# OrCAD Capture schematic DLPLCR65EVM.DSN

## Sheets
1 PAGE-05 DMD Power: size D
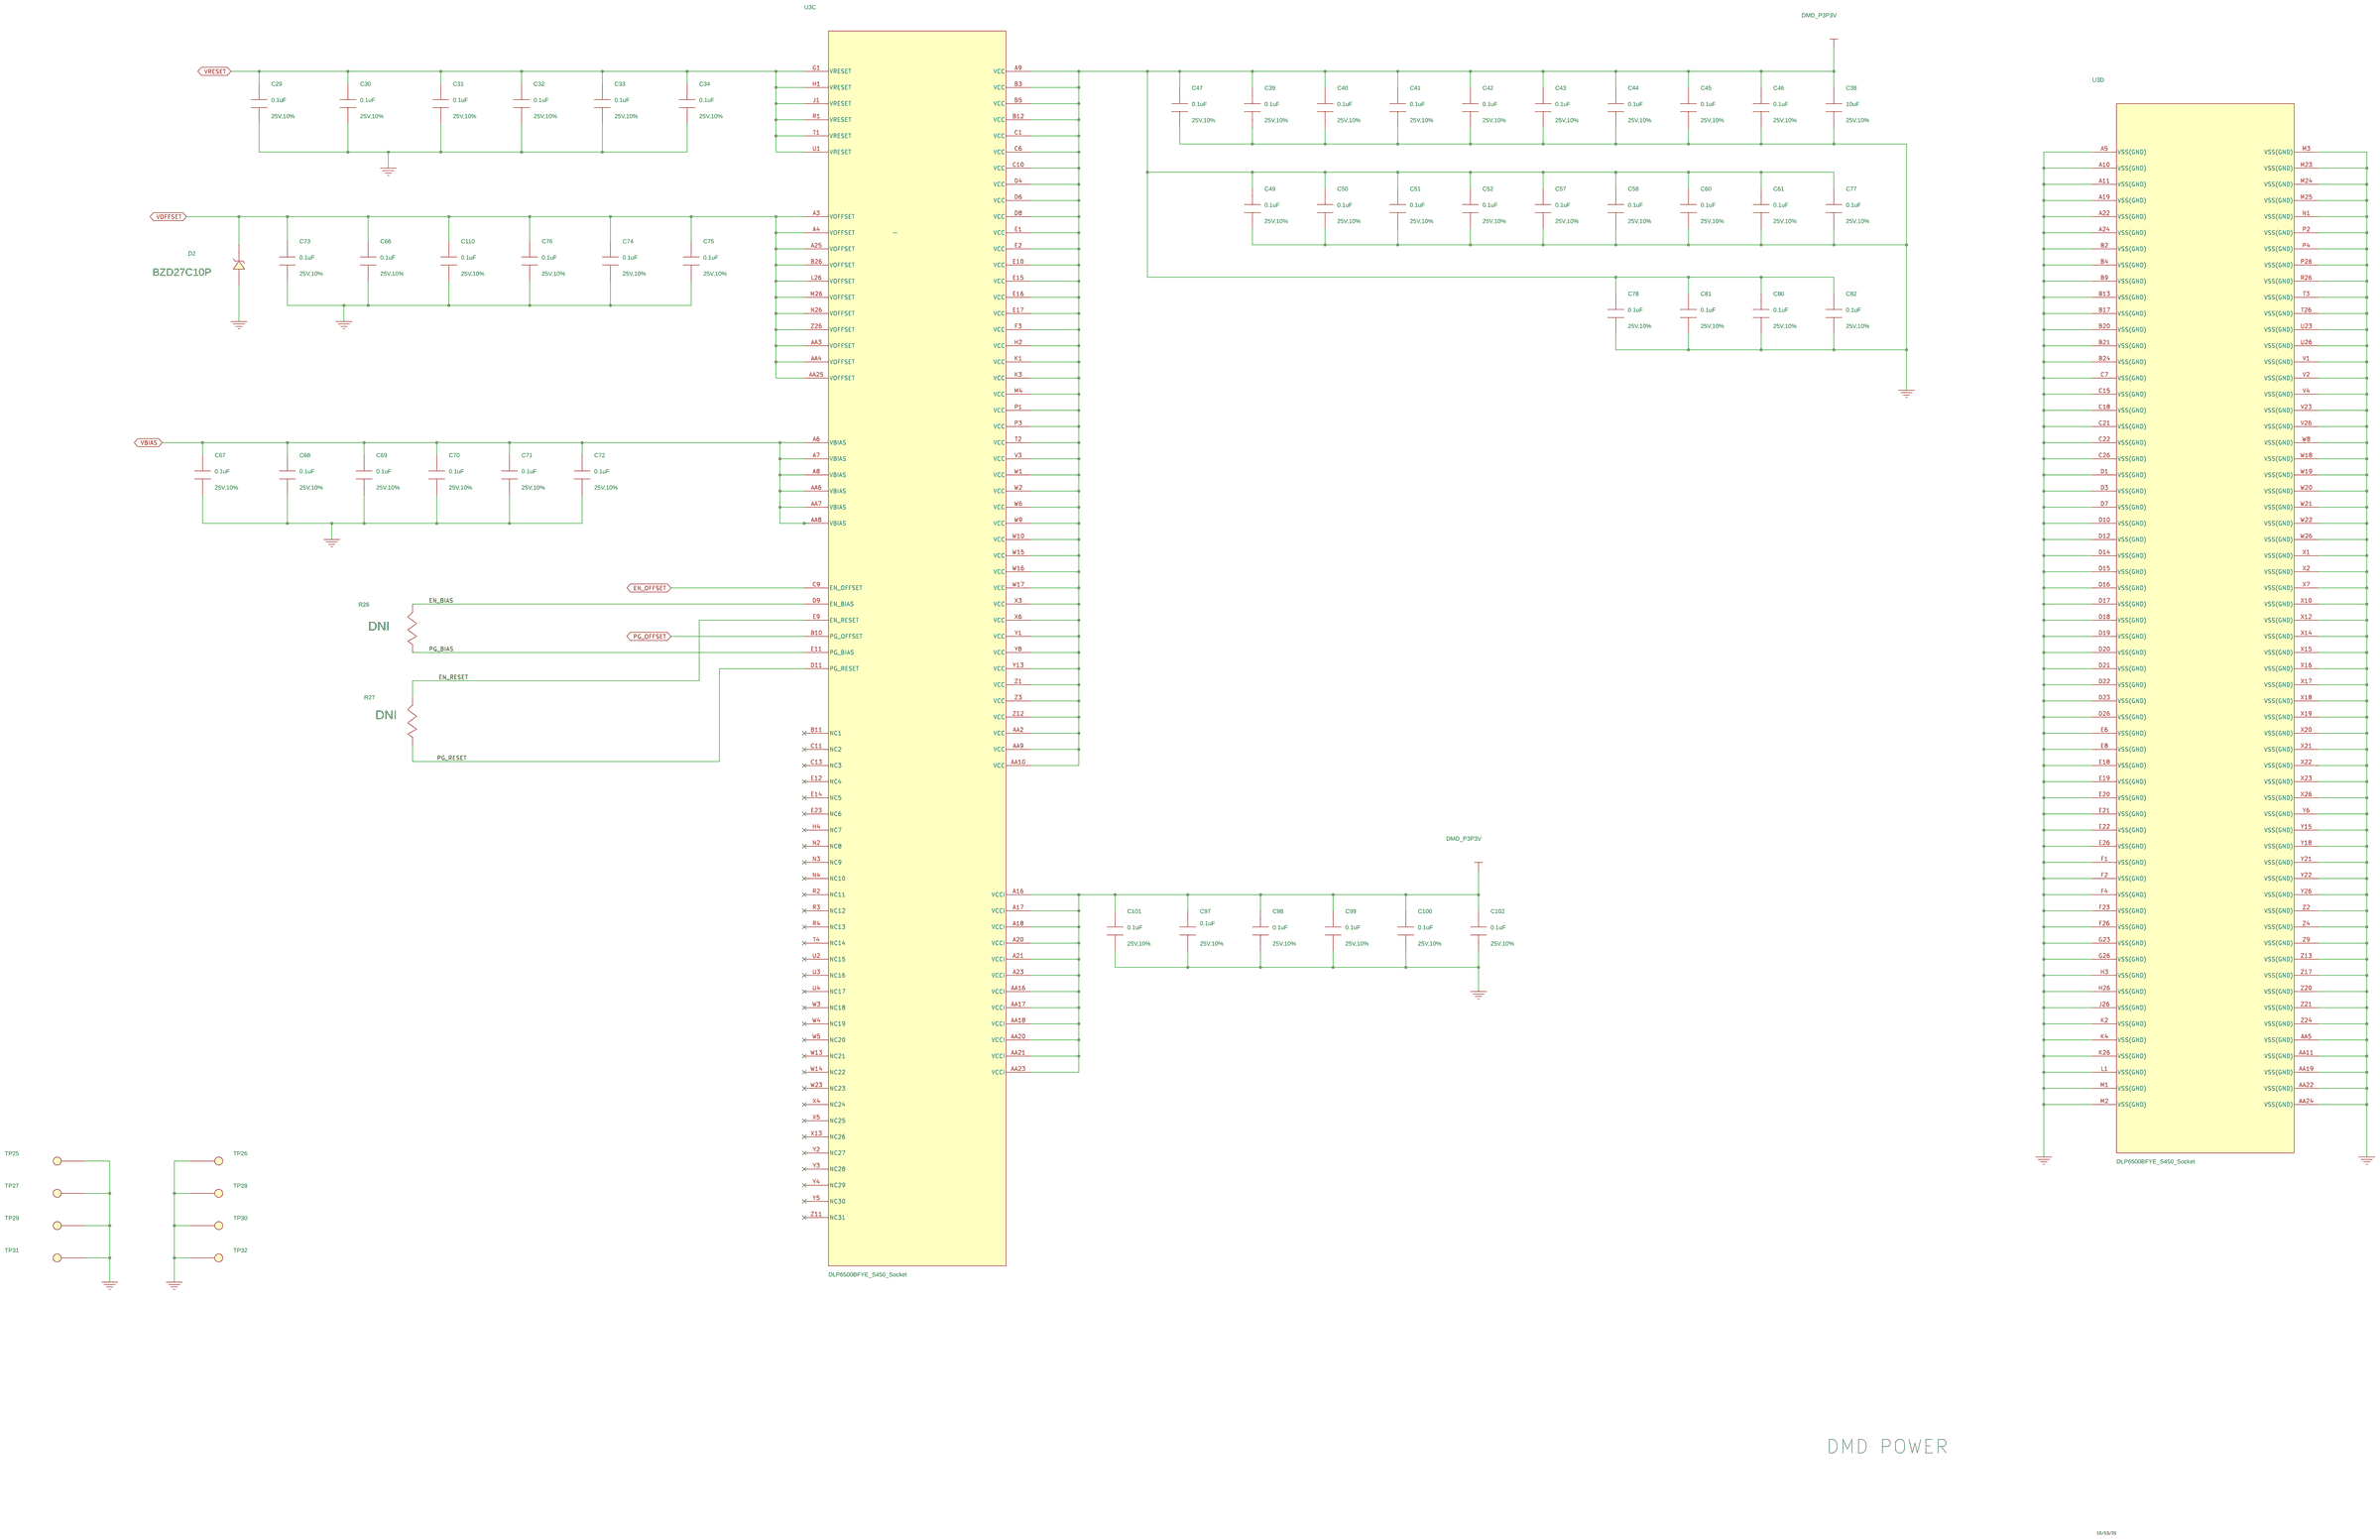
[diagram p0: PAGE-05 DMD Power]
2 PAGE-04 DMD Data Input: size D
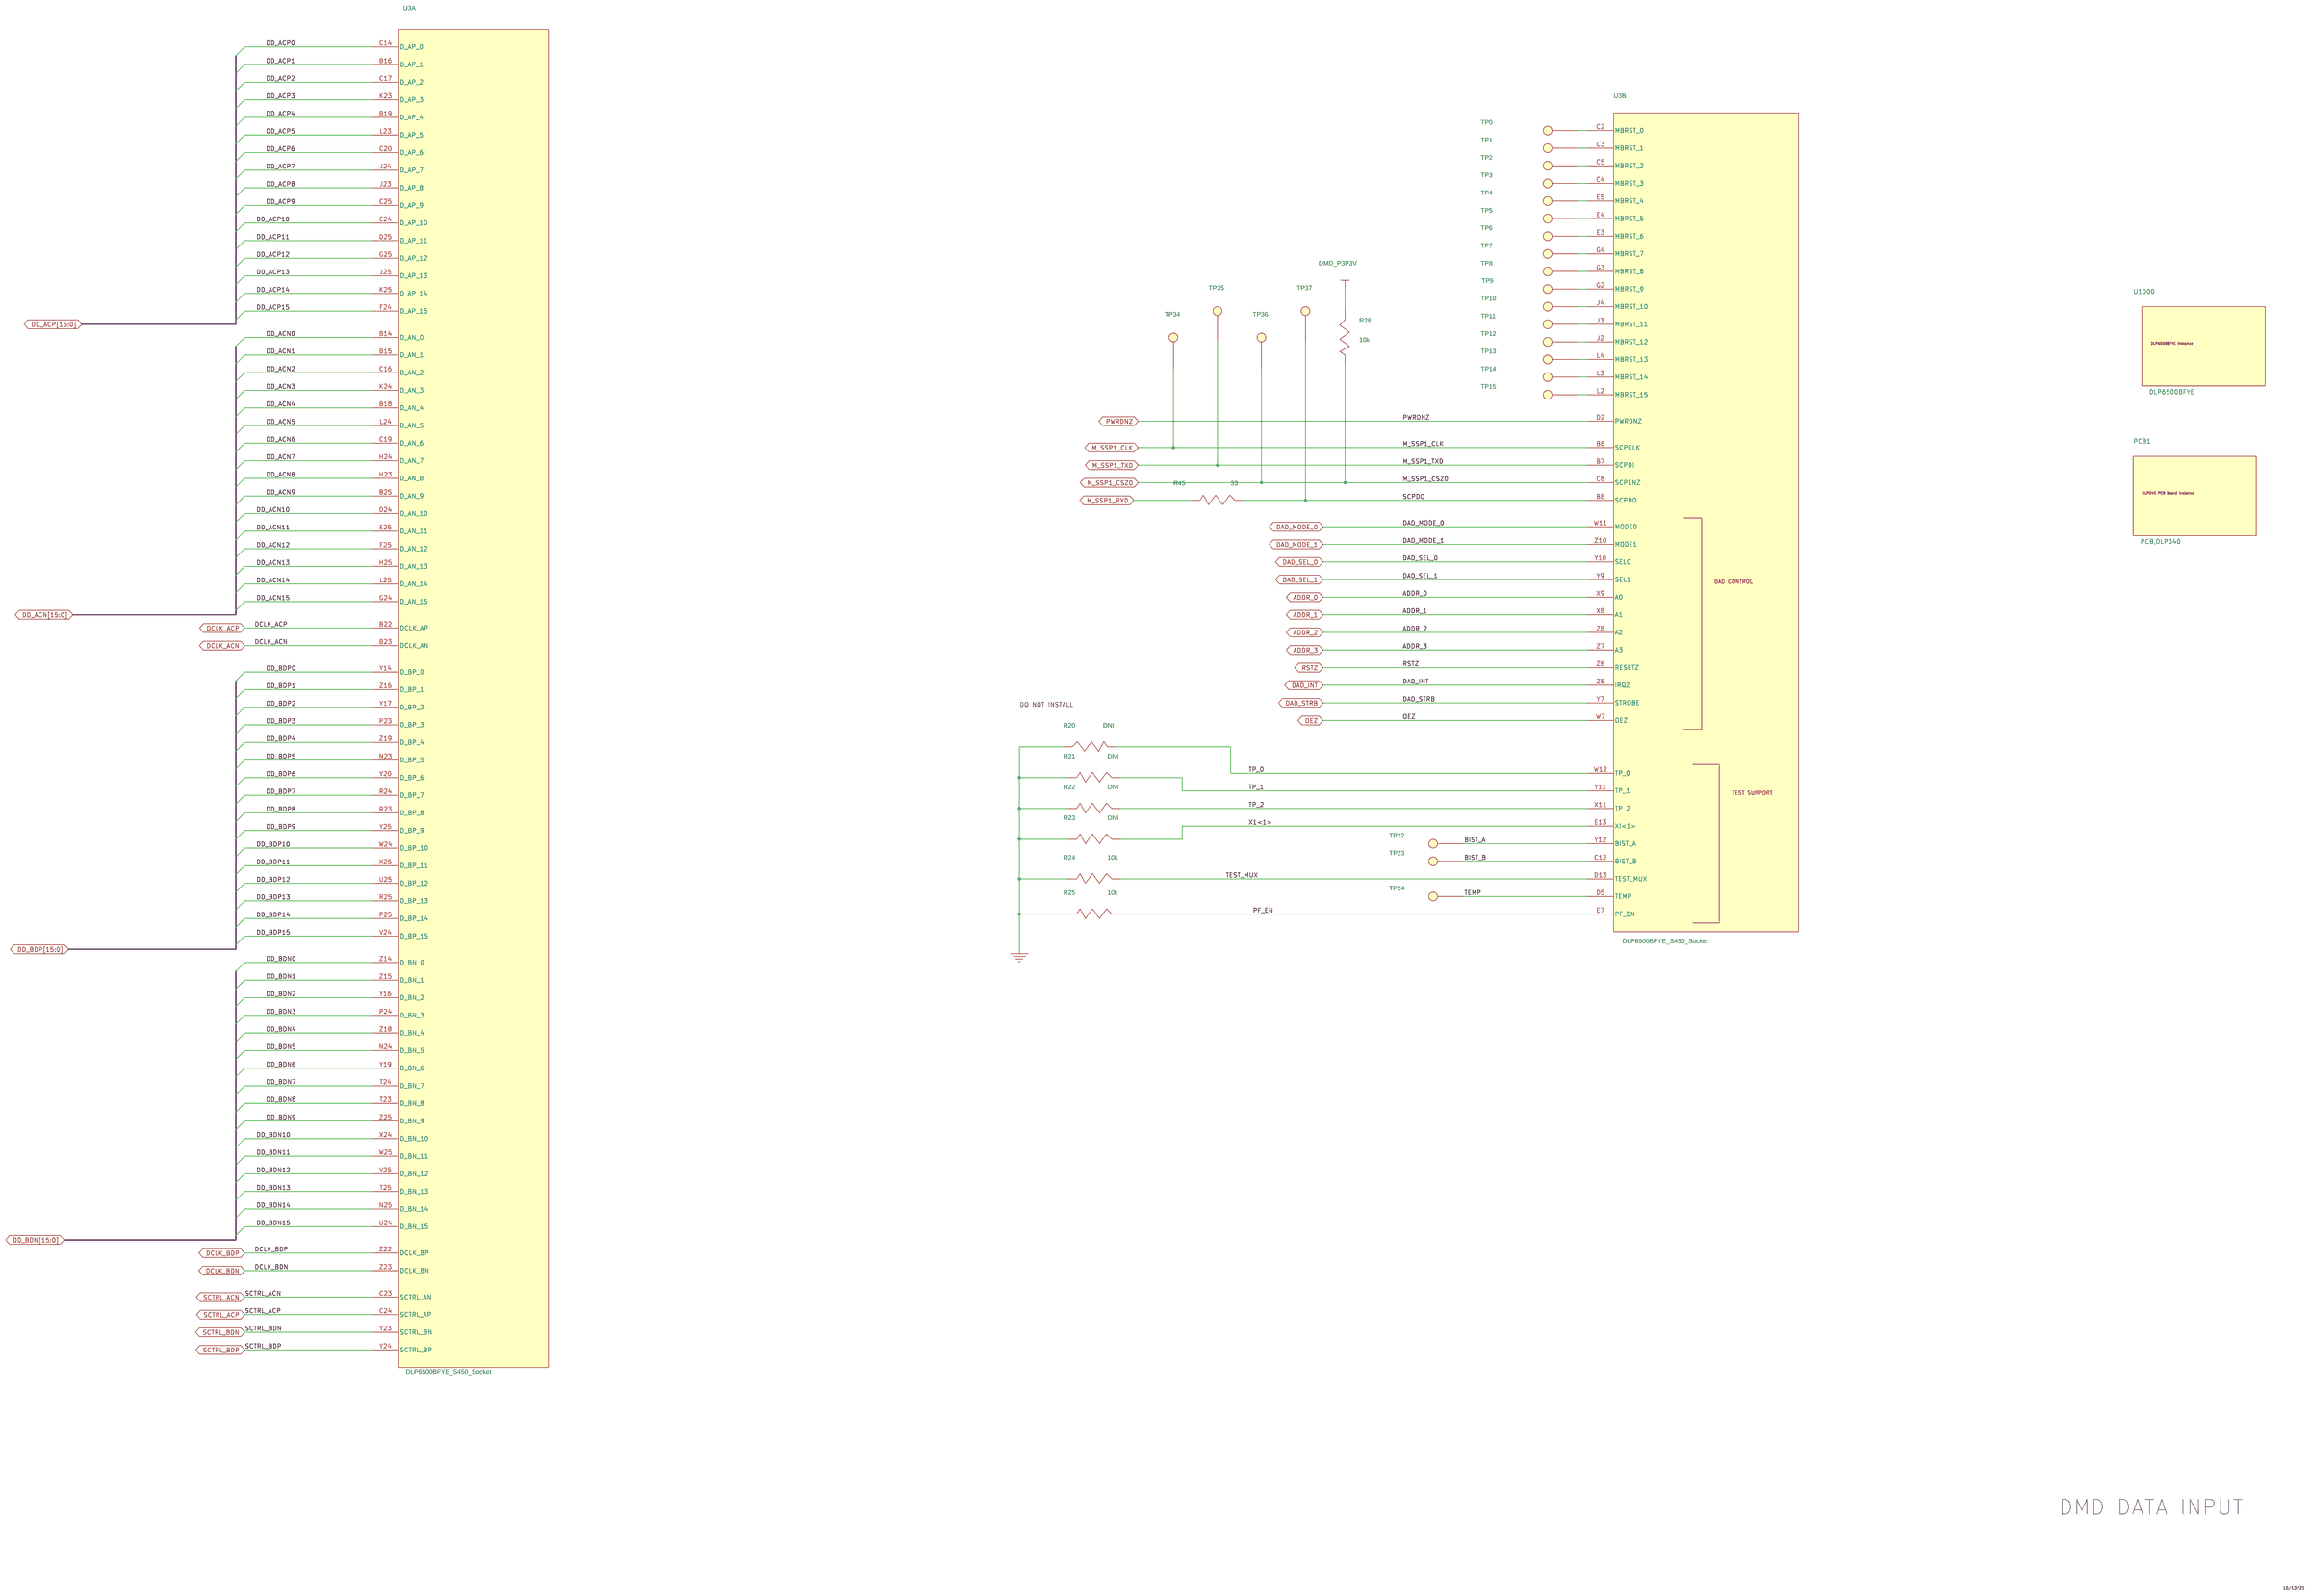
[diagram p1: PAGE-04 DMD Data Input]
3 PAGE-01 Title Page
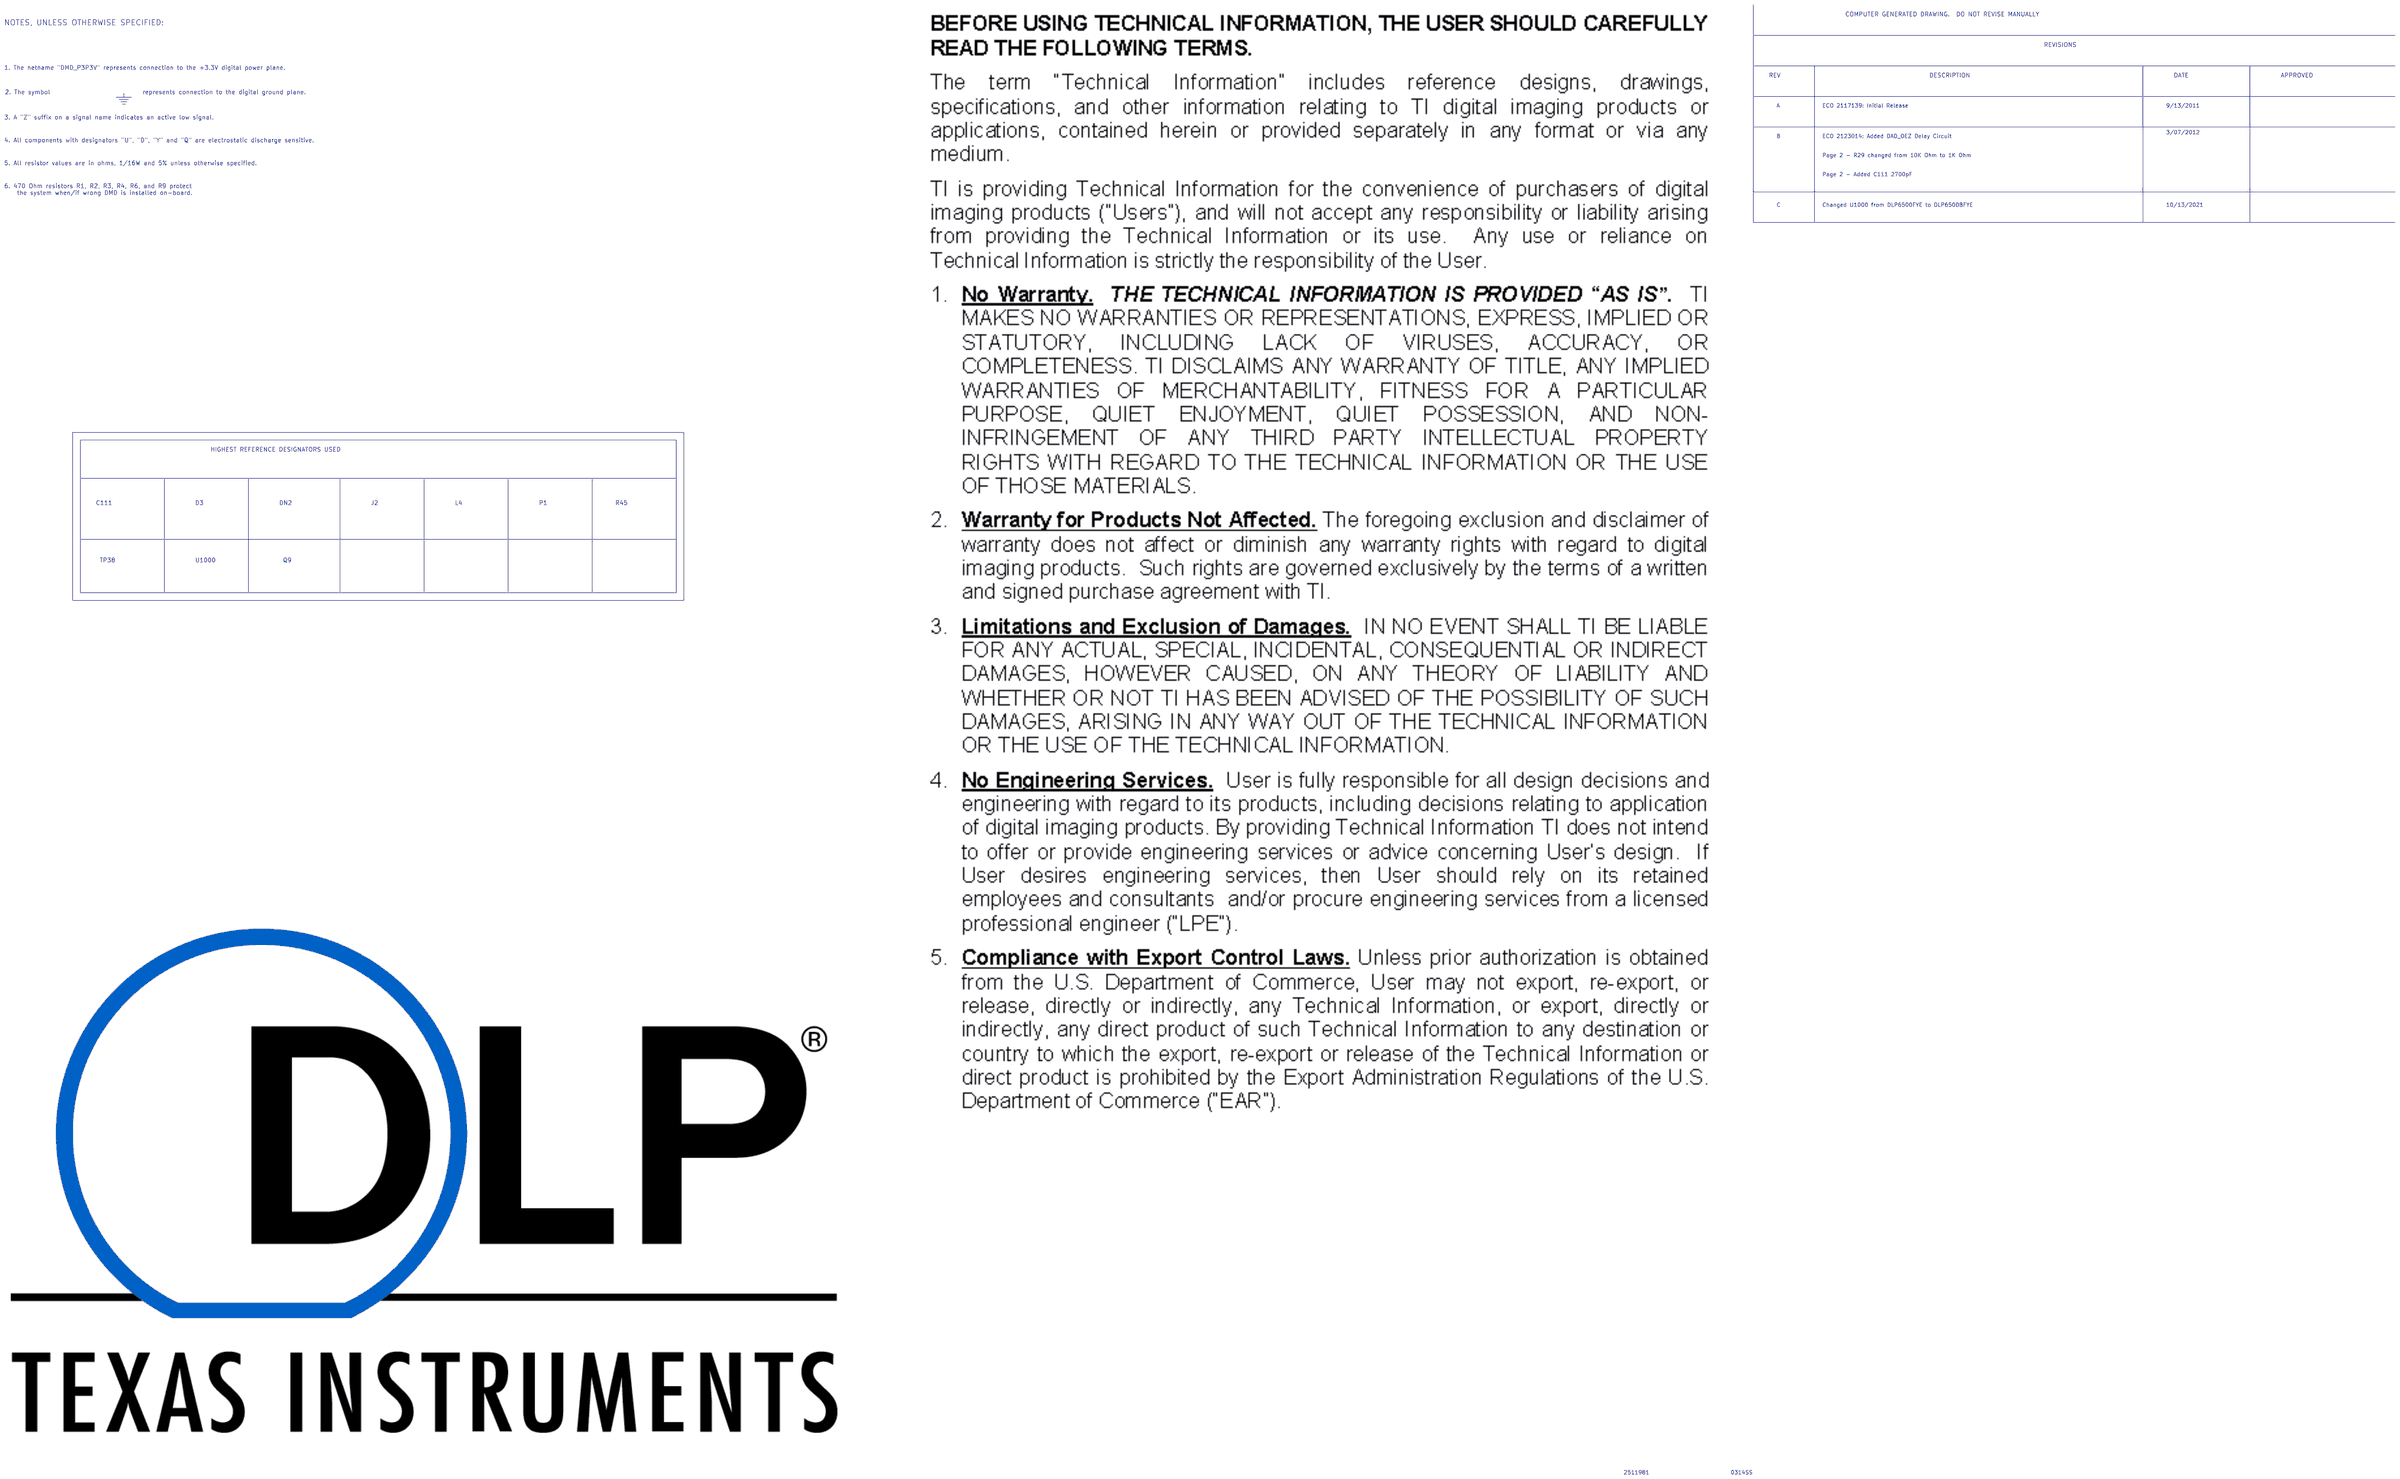
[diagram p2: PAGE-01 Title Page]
4 PAGE-03 DMD Power Supply: size D
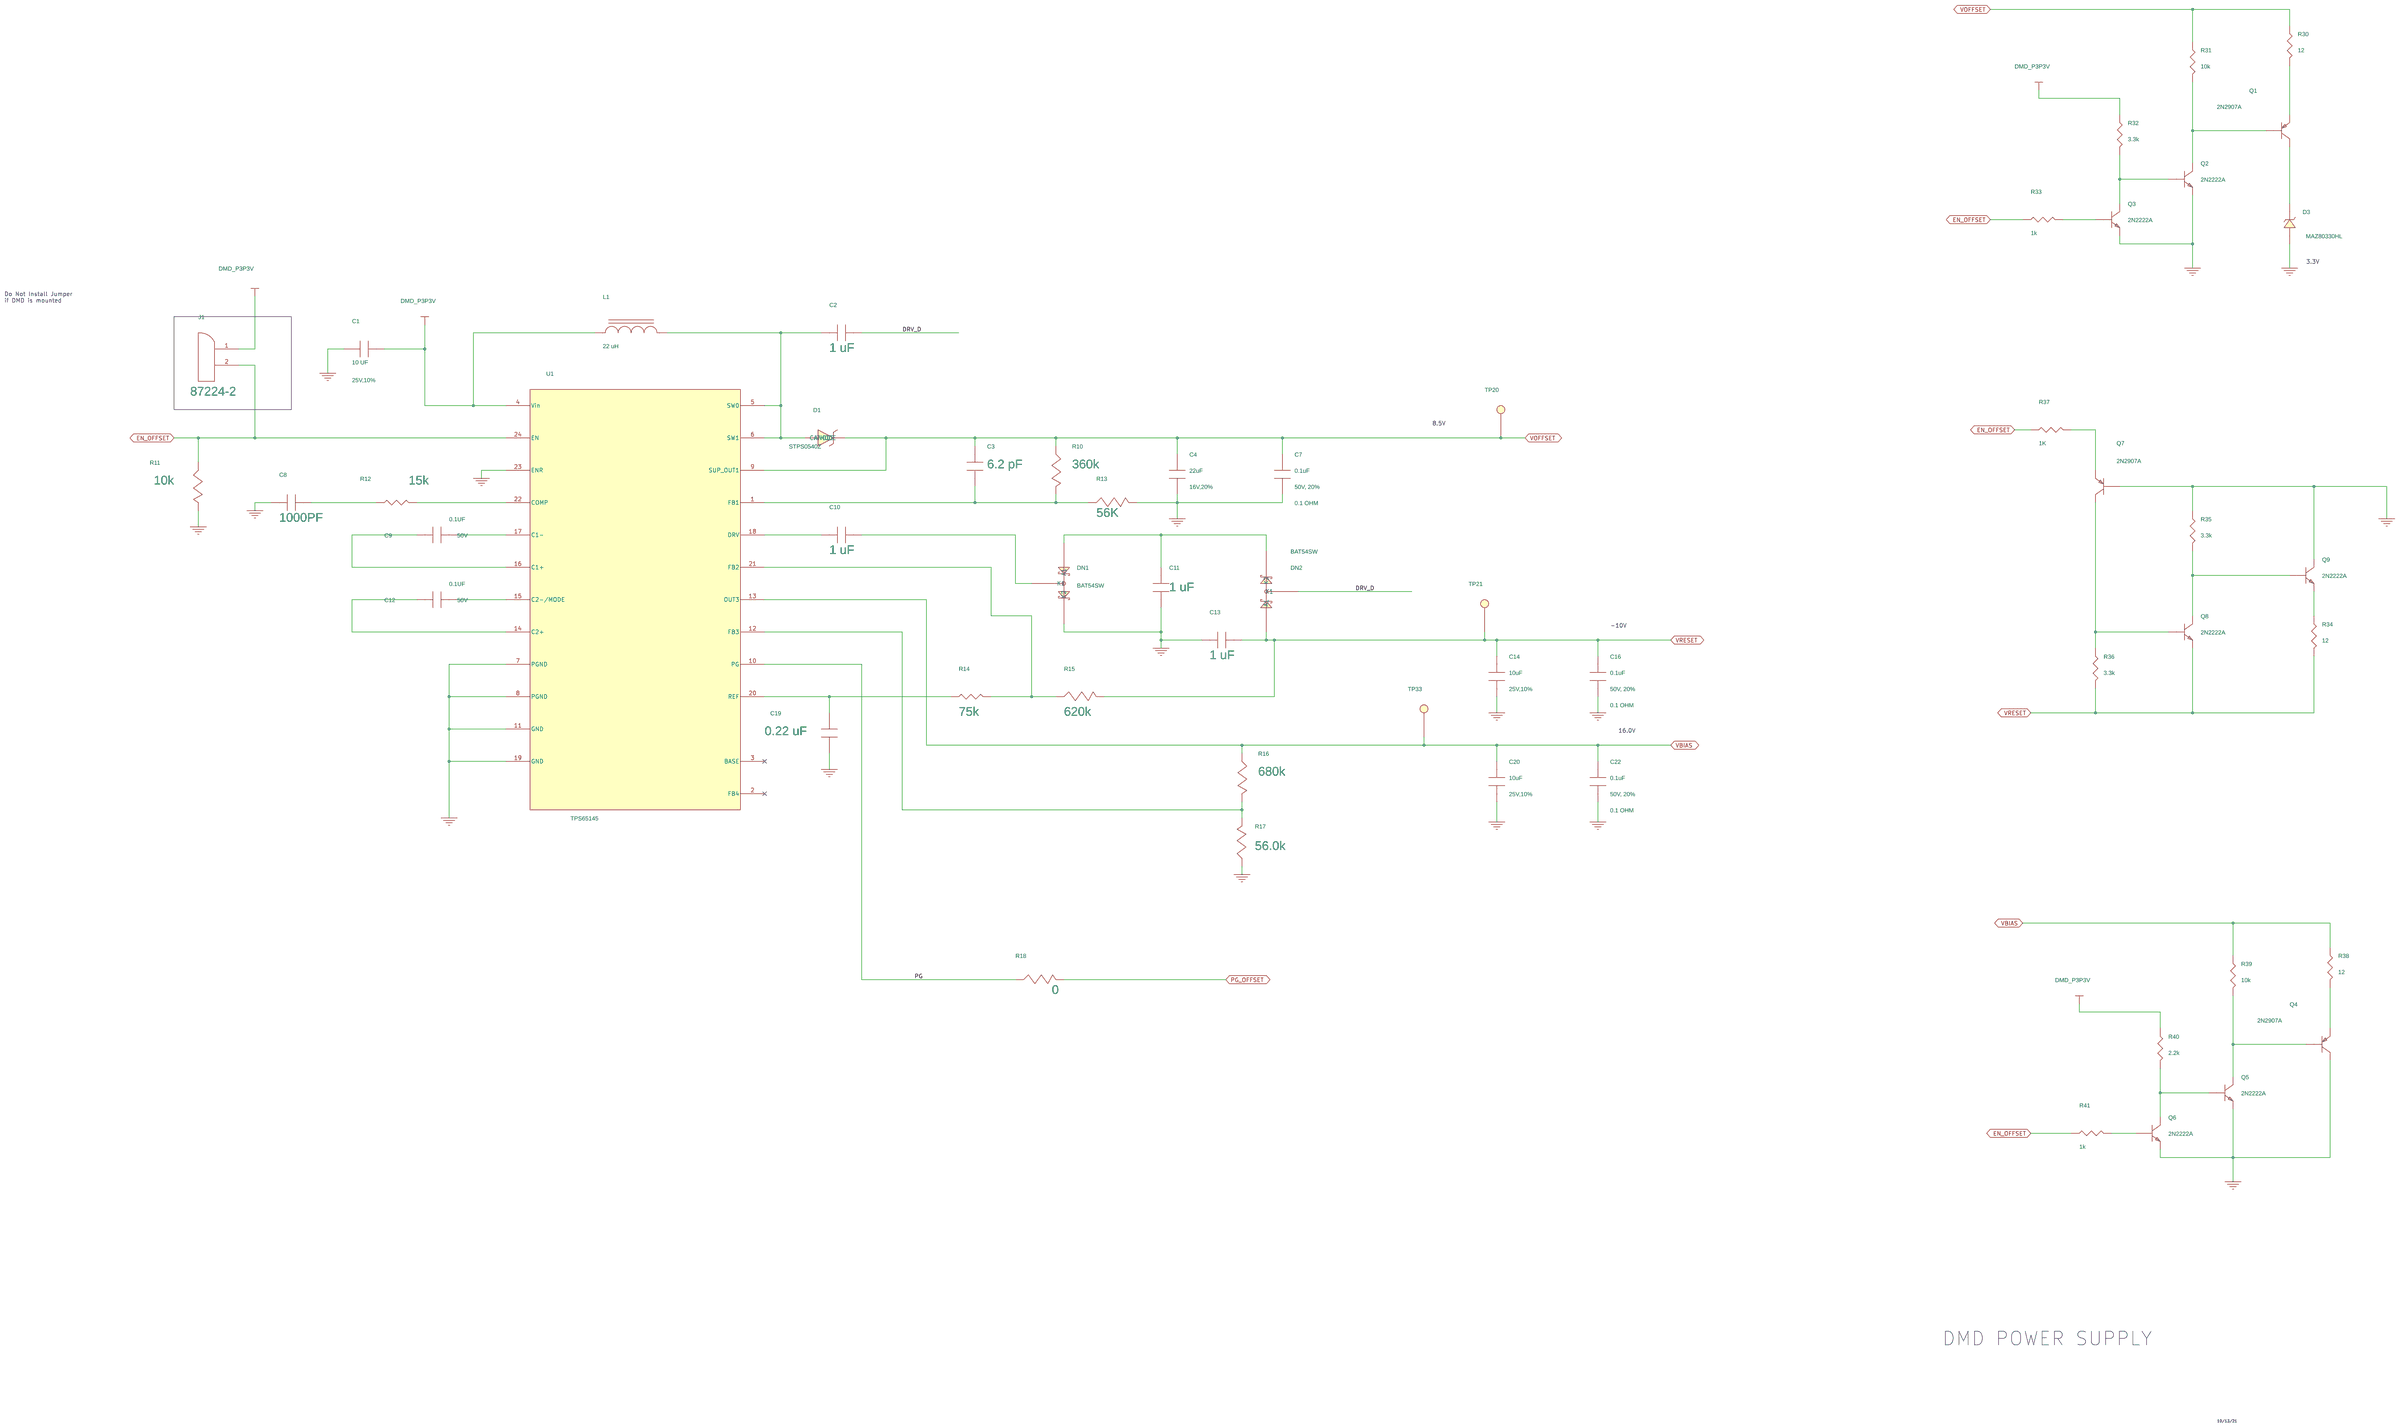
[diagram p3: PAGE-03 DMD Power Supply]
5 PAGE-02 Input Conn: size D
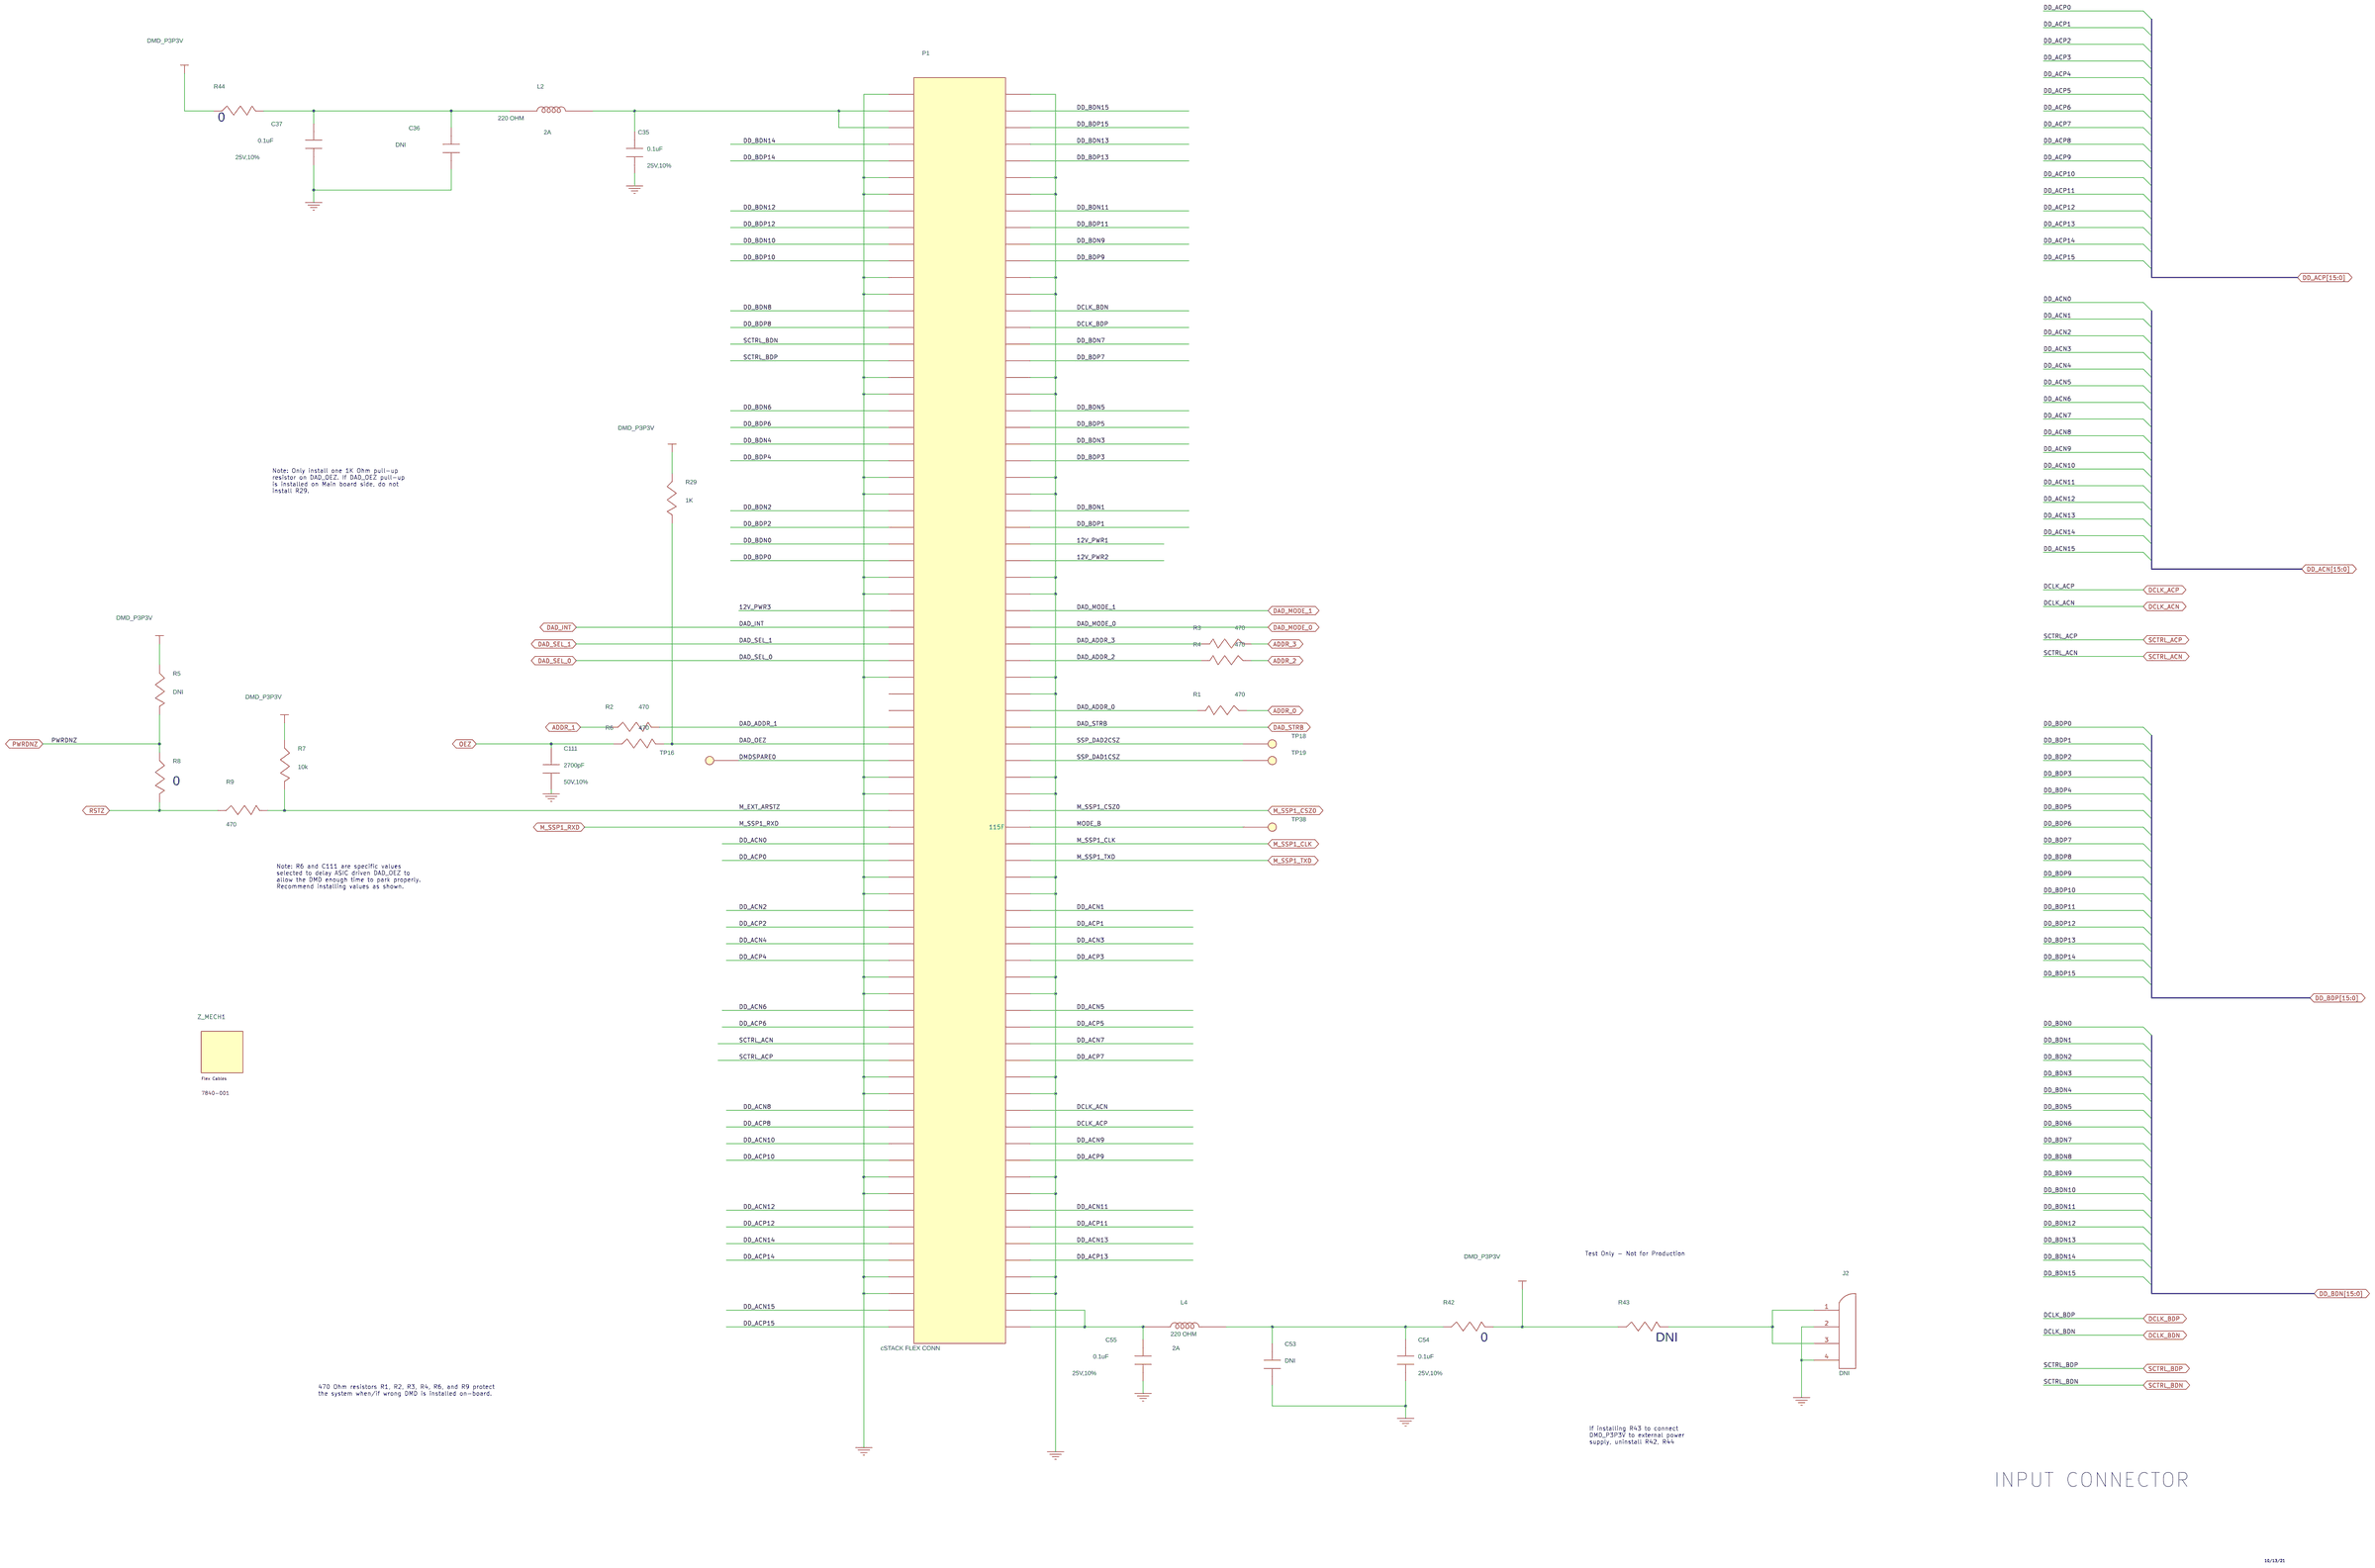
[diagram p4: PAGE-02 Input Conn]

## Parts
sheet PAGE-02 Input Conn
C35  0.1uF  [0603avx]
C36  DNI  [1210avx]
C37  0.1uF  [0603avx]
C53  DNI  [1210avx]
C54  0.1uF  [0603avx]
C55  0.1uF  [0603avx]
C111  2700pF  [0402avx]
J2  DNI  [cn4sip98ra]
L2  220 OHM  [0805avx]
L4  220 OHM  [0805avx]
P1  cSTACK FLEX CONN  [CN150CUSTOM_REVB-MOD-NO-MH]
R1  470  [0603avx]
R2  470  [0603avx]
R3  470  [0603avx]
R4  470  [0603avx]
R5  DNI  [0603avx]
R6  470  [0603avx]
R7  10k  [0603avx]
R8  0  [0603avx]
R9  470  [0603avx]
R29  1K  [0603avx]
R42  0  [1210avx]
R43  DNI  [1210avx]
R44  0  [1210avx]
TP16  Testpoint  [tp40_24]
TP18  Testpoint  [tp40_24]
TP19  Testpoint  [tp40_24]
TP38  Testpoint  [tp40_24]
Z_MECH1  MECH
sheet PAGE-03 DMD Power Supply
C1  10 UF  [1210avx]
C2  1 uF  [0603AVX]
C3  6.2 pF  [0402AVX]
C4  22uF  [1210]
C7  0.1uF  [0805avx]
C8  1000PF  [0805avx]
C9  0.1UF  [0805avx]
C10  1 uF  [0603AVX]
C11  1 uF  [0603AVX]
C12  0.1UF  [0805avx]
C13  1 uF  [0603AVX]
C14  10uF  [1210]
C16  0.1uF  [0805avx]
C19  0.22 uF  [0805AVX]
C20  10uF  [1210]
C22  0.1uF  [0805avx]
D1  STPS0540Z  [SOD123]
D3  MAZ80330HL  [S-MINI 2P]
DN1  BAT54SW  [sot323avx]
DN2  BAT54SW  [sot323avx]
J1  87224-2  [CN2SIP]
L1  22 uH  [dt1608a]
Q1  2N2907A  [SOT23-3]
Q2  2N2222A  [SOT23-3]
Q3  2N2222A  [SOT23-3]
Q4  2N2907A  [SOT23-3]
Q5  2N2222A  [SOT23-3]
Q6  2N2222A  [SOT23-3]
Q7  2N2907A  [SOT23-3]
Q8  2N2222A  [SOT23-3]
Q9  2N2222A  [SOT23-3]
R10  360k  [0603avx]
R11  10k  [0603avx]
R12  15k  [0603AVX]
R13  56K  [0603avx]
R14  75k  [0603avx]
R15  620k  [0603avx]
R16  680k  [0603avx]
R17  56.0k  [0603avx]
R18  0  [0603avx]
R30  12  [0603]
R31  10k  [0402]
R32  3.3k  [0402]
R33  1k  [0402]
R34  12  [0603]
R35  3.3k  [0402]
R36  3.3k  [0402]
R37  1K  [0402]
R38  12  [0603]
R39  10k  [0402]
R40  2.2k  [0402]
R41  1k  [0402]
TP20  Testpoint  [tp40_24]
TP21  Testpoint  [tp40_24]
TP33  Testpoint  [tp40_24]
U1  TPS65145  [SOIC24-PWP_TI]
sheet PAGE-04 DMD Data Input
PCB1  PCB,DLP040
R20  DNI  [0603avx]
R21  DNI  [0603avx]
R22  DNI  [0603avx]
R23  DNI  [0603avx]
R24  10k  [0603avx]
R25  10k  [0603avx]
R28  10k  [0603avx]
R45  33  [0603avx]
TP0  Testpoint  [tp-40]
TP1  Testpoint  [tp-40]
TP2  Testpoint  [tp-40]
TP3  Testpoint  [tp-40]
TP4  Testpoint  [tp-40]
TP5  Testpoint  [tp-40]
TP6  Testpoint  [tp-40]
TP7  Testpoint  [tp-40]
TP8  Testpoint  [tp-40]
TP9  Testpoint  [tp-40]
TP10  Testpoint  [tp-40]
TP11  Testpoint  [tp-40]
TP12  Testpoint  [tp-40]
TP13  Testpoint  [tp-40]
TP14  Testpoint  [tp-40]
TP15  Testpoint  [tp-40]
TP22  Testpoint  [tp-40]
TP23  Testpoint  [tp40_24]
TP24  Testpoint  [tp40_24]
TP34  Testpoint  [tp-40]
TP35  Testpoint  [tp-40]
TP36  Testpoint  [tp-40]
TP37  Testpoint  [tp-40]
U1000  DLP6500BFYE
sheet PAGE-05 DMD Power
C29  0.1uF  [0603avx]
C30  0.1uF  [0603avx]
C31  0.1uF  [0603avx]
C32  0.1uF  [0603avx]
C33  0.1uF  [0603avx]
C34  0.1uF  [0603avx]
C38  10uF  [1210]
C39  0.1uF  [0603avx]
C40  0.1uF  [0603avx]
C41  0.1uF  [0603avx]
C42  0.1uF  [0603avx]
C43  0.1uF  [0603avx]
C44  0.1uF  [0603avx]
C45  0.1uF  [0603avx]
C46  0.1uF  [0603avx]
C47  0.1uF  [0603avx]
C49  0.1uF  [0603avx]
C50  0.1uF  [0603avx]
C51  0.1uF  [0603avx]
C52  0.1uF  [0603avx]
C57  0.1uF  [0603avx]
C58  0.1uF  [0603avx]
C60  0.1uF  [0603avx]
C61  0.1uF  [0603avx]
C66  0.1uF  [0603avx]
C67  0.1uF  [0603avx]
C68  0.1uF  [0603avx]
C69  0.1uF  [0603avx]
C70  0.1uF  [0603avx]
C71  0.1uF  [0603avx]
C72  0.1uF  [0603avx]
C73  0.1uF  [0603avx]
C74  0.1uF  [0603avx]
C75  0.1uF  [0603avx]
C76  0.1uF  [0603avx]
C77  0.1uF  [0603avx]
C78  0.1uF  [0603avx]
C80  0.1uF  [0603avx]
C81  0.1uF  [0603avx]
C82  0.1uF  [0603avx]
C97  0.1uF  [0603avx]
C98  0.1uF  [0603avx]
C99  0.1uF  [0603avx]
C100  0.1uF  [0603avx]
C101  0.1uF  [0603avx]
C102  0.1uF  [0603avx]
C110  0.1uF  [0603avx]
D2  BZD27C10P  [BZD27C]
R26  DNI  [0603avx]
R27  DNI  [0603avx]
TP25  Testpoint  [tp40_24]
TP26  Testpoint  [tp40_24]
TP27  Testpoint  [tp40_24]
TP28  Testpoint  [tp40_24]
TP29  Testpoint  [tp40_24]
TP30  Testpoint  [tp40_24]
TP31  Testpoint  [tp40_24]
TP32  Testpoint  [tp40_24]
U3  DLP6500BFYE_S450_Socket  [temp]  (sections A,B,C,D)

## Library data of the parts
C29-C35 C37 C39-C47 C49-C52 C54 C55 C57 C58 C60 C61 C66-C78 C80-C82 C97-C102 C110 = CAP_NP_dsize: ESR: <ESR>; ICA_MFR_NAME: PANASONIC; ICA_PARTNUM: $$2075017$$ECJ1VB1E104K; MFG: AVX; Part Number: 06033C104KAT4A; Rating/Tolerance: 25V,10%
C36 C53 = CAP_NP_dsize: Do Not Install: Do Not Install; ESR: <ESR>; Part Number: GRM32DR61E106KA12L; Rating/Tolerance: 25V,10%
C111 = CAP_NP_dsize: ESR: <ESR>; ICA_MFR_NAME: PANASONIC; ICA_PARTNUM: $$2075017$$ECJ1VB1E104K; MFG: Yageo; Part Number: CC0402KRX7R9BB272; Rating/Tolerance: 50V,10%
J2 = CONN_0: CCA ITEM: 39; Do Not Install: Do Not Install; MFG: JST; Part Number: NEW-TMP-428
L2 L4 = FERRITE_L: CCA ITEM: 59; CURRENT: 2A; ICA_MFR_NAME: MURATA; ICA_PARTNUM: $$1507311$$BLM21PG221SG; MFG: Murata; Part Number: BLM21PG221SN1D
P1 = cSTACK_FLEX_CONN: MFG: Amphenol
R1-R4 R6 R9 = RESISTOR_dsize: CCA ITEM: 110; ICA_MFR_NAME: PANASONIC; ICA_PARTNUM: $$1785380$$ERJ-3GSYJ330V; MFG: Panasonic; Part Number: ERJ-3GEYJ471V; RATING/TOLERANCE: <RATING/TOLERANCE>
R5 R20-R23 = RESISTOR_dsize: CCA ITEM: 111; Do Not Install: Do Not Install; ICA_MFR_NAME: PANASONIC; ICA_PARTNUM: $$1784360$$ERJ-3GSYJ103; Part Number: ERJ-3GSYJ103; RATING/TOLERANCE: <RATING/TOLERANCE>
R7 R24 R25 R28 = RESISTOR_dsize: CCA ITEM: 111; ICA_MFR_NAME: PANASONIC; ICA_PARTNUM: $$1784360$$ERJ-3GSYJ103; MFG: Panasonic; Part Number: ERJ-3GEYJ103V; RATING/TOLERANCE: <RATING/TOLERANCE>
R8 R18 = RESISTOR_dsize: ICA_MFR_NAME: YAGEO; ICA_PARTNUM: $$482834$$RC0603JRF070R0; MFG: Panasonic; Part Number: ERJ-3GEY0R00V
R29 = RESISTOR_dsize: CCA ITEM: 111; ICA_MFR_NAME: PANASONIC; ICA_PARTNUM: $$1784360$$ERJ-3GSYJ103; MFG: Panasonic; Part Number: ERJ-3GEYJ102V; RATING/TOLERANCE: 5%
R42 R44 = RESISTOR_dsize: ICA_MFR_NAME: YAGEO; ICA_PARTNUM: $$482834$$RC0603JRF070R0; MFG: Vishay; Part Number: CRCW12100000Z0EA
R43 = RESISTOR_dsize: Do Not Install: Do Not Install; ICA_MFR_NAME: YAGEO; ICA_PARTNUM: $$482834$$RC0603JRF070R0; Part Number: CRCW12100000Z0EA
TP16 TP18 TP19 TP38 = Testpoint: Part Number: SA-TMP-148
Z_MECH1 = PCB: Flex Cables; MFG: Amphenol; Notes: Kitting item; Part Number: 7840-001
C1 = CAP_NP_dsize: ESR: <ESR>; MFG: TDK; Part Number: C3225X5R1E106K250AA; Rating/Tolerance: 25V,10%
C2 C10 C11 C13 = CAP_NP_dsize: MFG: AVX; Part Number: 06033D105KAT2A
C3 = CAP_NP_dsize: MFG: Murata; Part Number: GJM1555C1H6R2CB01D
C4 = CAP_NP_dsize: ESR: <ESR>; MFG: Taiyo Yuden; Rating/Tolerance: 16V,20%; part number: EMK325BJ226MM-T
C7 C16 C22 = CAP_NP_dsize: ESR: 0.1 OHM; ICA_MFR_NAME: NIC; ICA_PARTNUM: $$2075017$$NMC1206X7R104K50; MFG: AVX; Part Number: 08055C104MAT2A; Rating/Tolerance: 50V, 20%
C8 = CAP_NP_dsize: MFG: AVX; Part Number: 08055C102KAT2A
C9 C12 = CAP_NP_dsize: ESR: 0.1 OHM; ICA_MFR_NAME: NIC; ICA_PARTNUM: $$2075017$$NMC1206X7R104K50; MFG: AVX; Part Number: 08055C104MAT2A; Rating/Tolerance: 50V
C14 C20 C38 = CAP_NP_dsize: ESR: <ESR>; MFG: TDK; Rating/Tolerance: 25V,10%; part number: C3225X5R1E106K250AA
C19 = CAP_NP_dsize: MFG: TDK; Part Number: C2012X8R1E224K
D1 = DIODE_SCHOTTKY_dsize: MFG: STMicroelectronics
D3 = DIODE_ZENER: MFG: ON Semiconductor; Part Number: MM3Z3V3B
DN1 DN2 = BAT54SW: ICA_MFR_NAME: PHILIPS SEMICONDUCTOR; ICA_PARTNUM: $$1491280$$BAT54SW; MFG: Diode Inc
J1 = CONN_2PINS_dsize: MFG: TE Connectivity
L1 = INDUCTOR: MFG: Coilcraft; Part Number: DT1608C-223
Q1 Q4 Q7 = 2N2907A: MFG: Diode Inc; Part Number: MMBT2907A-7-F
Q2 Q3 Q5 Q6 Q8 Q9 = 2N2222A: MFG: Diode Inc; Part Number: MMBT2222A-7-F
R10 = RESISTOR_dsize: MFG: Panasonic; Part Number: ERJ-3GEYJ364V
R11 = RESISTOR_dsize: ICA_MFR_NAME: PANASONIC; ICA_PARTNUM: $$1784360$$ERJ-3GSYJ103; MFG: Panasonic; Part Number: ERJ-3GEYJ103V
R12 = RES: ICA_MFR_NAME: YAGEO; ICA_PARTNUM: $$2140285$$RC0603FR-0715KL; MFG: Yageo; Part Number: RC0603FR-0715KL
R13 = RESISTOR_dsize: ID: 52438849; MFG: Panasonic; Part Number: ERJ-3GEYJ563V
R14 = R: ICA_MFR_NAME: PANASONIC; ICA_PARTNUM: $$1784362$$ERJ-3GEYJ753; MFG: Panasonic; Part Number: ERJ-3GEYJ753
R15 = RESISTOR_dsize: MFG: Panasonic; Part Number: ERJ-3GEYJ624
R16 = RESISTOR_dsize: MFG: Panasonic; Part Number: ERJ-3GEYJ684V
R17 = RESISTOR_dsize: MFG: Panasonic; Part Number: ERJ-3GEYJ563V
R30 R34 R38 = RESISTOR: MFG: Panasonic; Part Number: ERJ-3GEYJ120V
R31 R39 = RESISTOR: MFG: Panasonic; Part Number: ERJ-2GEJ103X
R32 R35 R36 = RESISTOR: MFG: Panasonic; Part Number: ERJ-2GEJ332X
R33 R37 R41 = RESISTOR: MFG: Panasonic; Part Number: ERJ-2GEJ102X
R40 = RESISTOR: MFG: Panasonic; Part Number: ERJ-2GEJ222X
TP0-TP15 TP20-TP37 = Testpoint: Part Number: TMP-543
U1 = TPS65145: MFG: TI; Part Number: TPS65145PWP
PCB1 = DLP026_2: MFG: Any
R45 = RESISTOR_dsize: CCA ITEM: 111; ICA_MFR_NAME: PANASONIC; ICA_PARTNUM: $$1784360$$ERJ-3GSYJ103; MFG: Panasonic; Part Number: ERJ-3GEYJ330V; RATING/TOLERANCE: <RATING/TOLERANCE>
U1000 = DLP026_3: MFG: TI
D2 = DIODE_ZENER: ICA_MFR_NAME: Vishay; ICA_PARTNUM: $$2105147$$BZD27C10P; MFG: Vishay; Part Number: BZD27C110P-M3-18
R26 R27 = RESISTOR_dsize: Do Not Install: Do Not Install; ICA_MFR_NAME: YAGEO; ICA_PARTNUM: $$482834$$RC0603JRF070R0; Part Number: ERJ-3GEY0R00V
U3 = p65_1080p_2xLVDS_s600_DMD: MFG: FIT; part number: PZ14927-1541-01F

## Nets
12V_PWR1: P1.10D
12V_PWR2: P1.10E
12V_PWR3: P1.11B
GND: C1.1 C4.2 C7.2 C8.1 C11.1 C13.1 C14.2 C16.2 C19.2 C20.2 C22.2 C29.2 C30.2 C31.2 C32.2 C33.2 C34.2 C35.2 C36.2 C37.2 C38.2 C39.2 C40.2 C41.2 C42.2 C43.2 C44.2 C45.2 C46.2 C47.2 C49.2 C50.2 C51.2 C52.2 C53.2 C54.2 C55.2 C57.2 C58.2 C60.2 C61.2 C66.2 C67.2 C68.2 C69.2 C70.2 C71.2 C72.2 C73.2 C74.2 C75.2 C76.2 C77.2 C78.2 C80.2 C81.2 C82.2 C97.2 C98.2 C99.2 C100.2 C101.2 C102.2 C110.2 C111.2 D2.2(ANODE) D3.2(ANODE) DN1.2(K2) J2.2 J2.4 P1.1A P1.1D P1.2C P1.2F P1.3A P1.3D P1.4C P1.4F P1.5A P1.5D P1.6C P1.6F P1.7A P1.7D P1.8C P1.8F P1.9A P1.9D P1.10C P1.10F P1.11A P1.11D P1.12C P1.12F P1.13D P1.14C P1.14F P1.15A P1.15D P1.16C P1.16F P1.17A P1.17D P1.18C P1.18F P1.19A P1.19D P1.20C P1.20F P1.21A P1.21D P1.22C P1.22F P1.23A P1.23D P1.24C P1.24F P1.25A P1.25D Q2.1(EMITTER) Q3.1(EMITTER) Q4.3(COLLECTOR) Q5.1(EMITTER) Q6.1(EMITTER) Q7.2(BASE) Q9.3(COLLECTOR) R11.2 R13.2 R17.1 R20.1 R21.2 R22.2 R23.2 R24.2 R25.2 R35.1 TP25.1 TP26.1 TP27.1 TP28.1 TP29.1 TP30.1 TP31.1 TP32.1 U1.7(PGND) U1.8(PGND) U1.11(GND) U1.19(GND) U1.23(ENR) U3.A5(VSS(GND)) U3.A10(VSS(GND)) U3.A11(VSS(GND)) U3.A19(VSS(GND)) U3.A22(VSS(GND)) U3.A24(VSS(GND)) U3.AA5(VSS(GND)) U3.AA11(VSS(GND)) U3.AA19(VSS(GND)) U3.AA22(VSS(GND)) U3.AA24(VSS(GND)) U3.B2(VSS(GND)) U3.B4(VSS(GND)) U3.B9(VSS(GND)) U3.B13(VSS(GND)) U3.B17(VSS(GND)) U3.B20(VSS(GND)) U3.B21(VSS(GND)) U3.B24(VSS(GND)) U3.C7(VSS(GND)) U3.C15(VSS(GND)) U3.C18(VSS(GND)) U3.C21(VSS(GND)) U3.C22(VSS(GND)) U3.C26(VSS(GND)) U3.D1(VSS(GND)) U3.D3(VSS(GND)) U3.D7(VSS(GND)) U3.D10(VSS(GND)) U3.D12(VSS(GND)) U3.D14(VSS(GND)) U3.D15(VSS(GND)) U3.D16(VSS(GND)) U3.D17(VSS(GND)) U3.D18(VSS(GND)) U3.D19(VSS(GND)) U3.D20(VSS(GND)) U3.D21(VSS(GND)) U3.D22(VSS(GND)) U3.D23(VSS(GND)) U3.D26(VSS(GND)) U3.E6(VSS(GND)) U3.E8(VSS(GND)) U3.E18(VSS(GND)) U3.E19(VSS(GND)) U3.E20(VSS(GND)) U3.E21(VSS(GND)) U3.E22(VSS(GND)) U3.E26(VSS(GND)) U3.F1(VSS(GND)) U3.F2(VSS(GND)) U3.F4(VSS(GND)) U3.F23(VSS(GND)) U3.F26(VSS(GND)) U3.G23(VSS(GND)) U3.G26(VSS(GND)) U3.H3(VSS(GND)) U3.H26(VSS(GND)) U3.J26(VSS(GND)) U3.K2(VSS(GND)) U3.K4(VSS(GND)) U3.K26(VSS(GND)) U3.L1(VSS(GND)) U3.M1(VSS(GND)) U3.M2(VSS(GND)) U3.M3(VSS(GND)) U3.M23(VSS(GND)) U3.M24(VSS(GND)) U3.M25(VSS(GND)) U3.N1(VSS(GND)) U3.P2(VSS(GND)) U3.P4(VSS(GND)) U3.P26(VSS(GND)) U3.R26(VSS(GND)) U3.T3(VSS(GND)) U3.T26(VSS(GND)) U3.U23(VSS(GND)) U3.U26(VSS(GND)) U3.V1(VSS(GND)) U3.V2(VSS(GND)) U3.V4(VSS(GND)) U3.V23(VSS(GND)) U3.V26(VSS(GND)) U3.W8(VSS(GND)) U3.W18(VSS(GND)) U3.W19(VSS(GND)) U3.W20(VSS(GND)) U3.W21(VSS(GND)) U3.W22(VSS(GND)) U3.W26(VSS(GND)) U3.X1(VSS(GND)) U3.X2(VSS(GND)) U3.X7(VSS(GND)) U3.X10(VSS(GND)) U3.X12(VSS(GND)) U3.X14(VSS(GND)) U3.X15(VSS(GND)) U3.X16(VSS(GND)) U3.X17(VSS(GND)) U3.X18(VSS(GND)) U3.X19(VSS(GND)) U3.X20(VSS(GND)) U3.X21(VSS(GND)) U3.X22(VSS(GND)) U3.X23(VSS(GND)) U3.X26(VSS(GND)) U3.Y6(VSS(GND)) U3.Y15(VSS(GND)) U3.Y18(VSS(GND)) U3.Y21(VSS(GND)) U3.Y22(VSS(GND)) U3.Y26(VSS(GND)) U3.Z2(VSS(GND)) U3.Z4(VSS(GND)) U3.Z9(VSS(GND)) U3.Z13(VSS(GND)) U3.Z17(VSS(GND)) U3.Z20(VSS(GND)) U3.Z21(VSS(GND)) U3.Z24(VSS(GND))
13A: P1.13A
13B: P1.13B
ADDR_0: R1.1 U3.X9(A0)
ADDR_1: R2.1 U3.X8(A1)
ADDR_2: R4.1 U3.Z8(A2)
ADDR_3: R3.1 U3.Z7(A3)
BIST_A: TP22.1 U3.Y12(BIST_A)
BIST_B: TP23.1 U3.C12(BIST_B)
DAD_ADDR_0: P1.13E R1.2
DAD_ADDR_1: P1.13C R2.2
DAD_ADDR_2: P1.12E R4.2
DAD_ADDR_3: P1.12D R3.2
DAD_INT: P1.11C U3.Z5(IRQZ)
DAD_MODE_0: P1.11F U3.W11(MODE0)
DAD_MODE_1: P1.11E U3.Z10(MODE1)
DAD_OEZ: P1.14A R6.2 R29.2
DAD_SEL_0: P1.12B U3.Y10(SEL0)
DAD_SEL_1: P1.12A U3.Y9(SEL1)
DAD_STRB: P1.13F U3.Y7(STROBE)
DCLK_ACN: P1.21E U3.B23(DCLK_AN)
DCLK_ACP: P1.21F U3.B22(DCLK_AP)
DCLK_BDN: P1.5E U3.Z23(DCLK_BN)
DCLK_BDP: P1.5F U3.Z22(DCLK_BP)
DD_ACN0: P1.16A U3.B14(D_AN_0)
DD_ACN1: P1.17E U3.B15(D_AN_1)
DD_ACN2: P1.17B U3.C16(D_AN_2)
DD_ACN3: P1.18D U3.K24(D_AN_3)
DD_ACN4: P1.18A U3.B18(D_AN_4)
DD_ACN5: P1.19E U3.L24(D_AN_5)
DD_ACN6: P1.19B U3.C19(D_AN_6)
DD_ACN7: P1.20D U3.H24(D_AN_7)
DD_ACN8: P1.21B U3.H23(D_AN_8)
DD_ACN9: P1.22D U3.B25(D_AN_9)
DD_ACN10: P1.22A U3.D24(D_AN_10)
DD_ACN11: P1.23E U3.E25(D_AN_11)
DD_ACN12: P1.23B U3.F25(D_AN_12)
DD_ACN13: P1.24D U3.H25(D_AN_13)
DD_ACN14: P1.24A U3.L25(D_AN_14)
DD_ACN15: P1.25B U3.G24(D_AN_15)
DD_ACP0: P1.16B U3.C14(D_AP_0)
DD_ACP1: P1.17F U3.B16(D_AP_1)
DD_ACP2: P1.17C U3.C17(D_AP_2)
DD_ACP3: P1.18E U3.K23(D_AP_3)
DD_ACP4: P1.18B U3.B19(D_AP_4)
DD_ACP5: P1.19F U3.L23(D_AP_5)
DD_ACP6: P1.19C U3.C20(D_AP_6)
DD_ACP7: P1.20E U3.J24(D_AP_7)
DD_ACP8: P1.21C U3.J23(D_AP_8)
DD_ACP9: P1.22E U3.C25(D_AP_9)
DD_ACP10: P1.22B U3.E24(D_AP_10)
DD_ACP11: P1.23F U3.D25(D_AP_11)
DD_ACP12: P1.23C U3.G25(D_AP_12)
DD_ACP13: P1.24E U3.J25(D_AP_13)
DD_ACP14: P1.24B U3.K25(D_AP_14)
DD_ACP15: P1.25C U3.F24(D_AP_15)
DD_BDN0: P1.10A U3.Z14(D_BN_0)
DD_BDN1: P1.9E U3.Z15(D_BN_1)
DD_BDN2: P1.9B U3.Y16(D_BN_2)
DD_BDN3: P1.8D U3.P24(D_BN_3)
DD_BDN4: P1.8A U3.Z18(D_BN_4)
DD_BDN5: P1.7E U3.N24(D_BN_5)
DD_BDN6: P1.7B U3.Y19(D_BN_6)
DD_BDN7: P1.6D U3.T24(D_BN_7)
DD_BDN8: P1.5B U3.T23(D_BN_8)
DD_BDN9: P1.4D U3.Z25(D_BN_9)
DD_BDN10: P1.4A U3.X24(D_BN_10)
DD_BDN11: P1.3E U3.W25(D_BN_11)
DD_BDN12: P1.3B U3.V25(D_BN_12)
DD_BDN13: P1.2D U3.T25(D_BN_13)
DD_BDN14: P1.2A U3.N25(D_BN_14)
DD_BDN15: P1.1E U3.U24(D_BN_15)
DD_BDP0: P1.10B U3.Y14(D_BP_0)
DD_BDP1: P1.9F U3.Z16(D_BP_1)
DD_BDP2: P1.9C U3.Y17(D_BP_2)
DD_BDP3: P1.8E U3.P23(D_BP_3)
DD_BDP4: P1.8B U3.Z19(D_BP_4)
DD_BDP5: P1.7F U3.N23(D_BP_5)
DD_BDP6: P1.7C U3.Y20(D_BP_6)
DD_BDP7: P1.6E U3.R24(D_BP_7)
DD_BDP8: P1.5C U3.R23(D_BP_8)
DD_BDP9: P1.4E U3.Y25(D_BP_9)
DD_BDP10: P1.4B U3.W24(D_BP_10)
DD_BDP11: P1.3F U3.X25(D_BP_11)
DD_BDP12: P1.3C U3.U25(D_BP_12)
DD_BDP13: P1.2E U3.R25(D_BP_13)
DD_BDP14: P1.2B U3.P25(D_BP_14)
DD_BDP15: P1.1F U3.V24(D_BP_15)
DMD_P3P3V: C1.2 C38.1 C39.1 C40.1 C41.1 C42.1 C43.1 C44.1 C45.1 C46.1 C47.1 C49.1 C50.1 C51.1 C52.1 C57.1 C58.1 C60.1 C61.1 C77.1 C78.1 C80.1 C81.1 C82.1 C97.1 C98.1 C99.1 C100.1 C101.1 C102.1 J1.1 L1.1 R5.1 R7.1 R28.1 R29.1 R32.1 R40.1 R42.2 R43.1 R44.1 U1.4(Vin) U3.A9(VCC) U3.A16(VCCI) U3.A17(VCCI) U3.A18(VCCI) U3.A20(VCCI) U3.A21(VCCI) U3.A23(VCCI) U3.AA2(VCC) U3.AA9(VCC) U3.AA10(VCC) U3.AA16(VCCI) U3.AA17(VCCI) U3.AA18(VCCI) U3.AA20(VCCI) U3.AA21(VCCI) U3.AA23(VCCI) U3.B3(VCC) U3.B5(VCC) U3.B12(VCC) U3.C1(VCC) U3.C6(VCC) U3.C10(VCC) U3.D4(VCC) U3.D6(VCC) U3.D8(VCC) U3.E1(VCC) U3.E2(VCC) U3.E10(VCC) U3.E15(VCC) U3.E16(VCC) U3.E17(VCC) U3.F3(VCC) U3.H2(VCC) U3.K1(VCC) U3.K3(VCC) U3.M4(VCC) U3.P1(VCC) U3.P3(VCC) U3.T2(VCC) U3.V3(VCC) U3.W1(VCC) U3.W2(VCC) U3.W6(VCC) U3.W9(VCC) U3.W10(VCC) U3.W15(VCC) U3.W16(VCC) U3.W17(VCC) U3.X3(VCC) U3.X6(VCC) U3.Y1(VCC) U3.Y8(VCC) U3.Y13(VCC) U3.Z1(VCC) U3.Z3(VCC) U3.Z12(VCC)
DMDSPARE0: P1.14B TP16.1
DRV_D: C2.1 DN2.3(K1)
EN_BIAS: R26.1 U3.D9(EN_BIAS)
EN_OFFSET: J1.2 R11.1 R33.1 R37.1 R41.1 U1.24(EN) U3.C9(EN_OFFSET)
EN_RESET: R27.1 U3.E9(EN_RESET)
M_EXT_ARSTZ: P1.15B R7.2 R9.2
M_SSP1_CLK: P1.16D TP34.1 U3.B6(SCPCLK)
M_SSP1_CSZ0: P1.15E R28.2 TP36.1 U3.C8(SCPENZ)
M_SSP1_RXD: P1.15C R45.2
M_SSP1_TXD: P1.16E TP35.1 U3.B7(SCPDI)
MODE_B: P1.15F(115F) TP38.1
OEZ: C111.1 R6.1 U3.W7(OEZ)
PF_EN: R25.1 U3.E7(PF_EN)
PG: R18.1 U1.10(PG)
PG_BIAS: R26.2 U3.E11(PG_BIAS)
PG_OFFSET: R18.2 U3.B10(PG_OFFSET)
PG_RESET: R27.2 U3.D11(PG_RESET)
PWRDNZ: R5.2 R8.1 U3.D2(PWRDNZ)
RSTZ: R8.2 R9.1 U3.Z6(RESETZ)
SCPDO: R45.1 TP37.1 U3.B8(SCPDO)
SCTRL_ACN: P1.20A U3.C23(SCTRL_AN)
SCTRL_ACP: P1.20B U3.C24(SCTRL_AP)
SCTRL_BDN: P1.6A U3.Y23(SCTRL_BN)
SCTRL_BDP: P1.6B U3.Y24(SCTRL_BP)
SSP_DAD1CSZ: P1.14E TP19.1
SSP_DAD2CSZ: P1.14D TP18.1
TEMP: TP24.1 U3.D5(TEMP)
TEST_MUX: R24.1 U3.D13(TEST_MUX)
TP_0: R20.2 U3.W12(TP_0)
TP_1: R21.1 U3.Y11(TP_1)
TP_2: R22.1 U3.X11(TP_2)
VBIAS: C20.1 C22.1 C67.1 C68.1 C69.1 C70.1 C71.1 C72.1 R16.1 R38.1 R39.1 TP33.1 U1.13(OUT3) U3.A6(VBIAS) U3.A7(VBIAS) U3.A8(VBIAS) U3.AA6(VBIAS) U3.AA7(VBIAS) U3.AA8(VBIAS)
VOFFSET: C3.1 C4.1 C7.1 C66.1 C73.1 C74.1 C75.1 C76.1 C110.1 D1.2(CATHODE) D2.1(CATHODE) R10.1 R30.1 R31.1 TP20.1 U1.9(SUP_OUT1) U3.A3(VOFFSET) U3.A4(VOFFSET) U3.A25(VOFFSET) U3.AA3(VOFFSET) U3.AA4(VOFFSET) U3.AA25(VOFFSET) U3.B26(VOFFSET) U3.L26(VOFFSET) U3.M26(VOFFSET) U3.N26(VOFFSET) U3.Z26(VOFFSET)
VRESET: C13.2 C14.1 C16.1 C29.1 C30.1 C31.1 C32.1 C33.1 C34.1 DN2.1(A1) Q8.1(EMITTER) R15.2 R34.2 R36.2 TP21.1 U3.G1(VRESET) U3.H1(VRESET) U3.J1(VRESET) U3.R1(VRESET) U3.T1(VRESET) U3.U1(VRESET)
X1<1>: R23.1 U3.E13(XI<1>)
N19230788: C3.2 R10.2 R13.1 U1.1(FB1)
N19264879: R16.2 R17.2 U1.12(FB3)
N19342809: C9.1 U1.16(C1+)
N19398726: C11.2 DN1.1(A1) DN2.2(K2)
N19416298: C10.2 DN1.3(K1)
N19422220: C8.2 R12.1
N19924640: C9.2 U1.17(C1-)
N19929772: C12.2 U1.15(C2-/MODE)
N19929785: C12.1 U1.14(C2+)
N19963203: R12.2 U1.22(COMP)
N19982077: C2.2 D1.1(ANODE) L1.2 U1.5(SW0) U1.6(SW1)
N20020334: C10.1 U1.18(DRV)
N20050588: C19.1 R14.1 U1.20(REF)
N20051083: R14.2 R15.1 U1.21(FB2)
N23531331: TP0.1 U3.C2(MBRST_0)
N23531911: TP1.1 U3.C3(MBRST_1)
N23532560: TP2.1 U3.C5(MBRST_2)
N23533211: TP3.1 U3.C4(MBRST_3)
N23533864: TP4.1 U3.E5(MBRST_4)
N23534519: TP5.1 U3.E4(MBRST_5)
N23535176: TP6.1 U3.E3(MBRST_6)
N23535835: TP7.1 U3.G4(MBRST_7)
N23536496: TP8.1 U3.G3(MBRST_8)
N23537159: TP9.1 U3.G2(MBRST_9)
N23539077: TP10.1 U3.J4(MBRST_10)
N23539749: TP11.1 U3.J3(MBRST_11)
N23540418: TP12.1 U3.J2(MBRST_12)
N23541762: TP14.1 U3.L3(MBRST_14)
N23542437: TP15.1 U3.L2(MBRST_15)
N23544675: TP13.1 U3.L4(MBRST_13)
N24153326: Q2.2(BASE) Q3.3(COLLECTOR) R32.2
N24162766: Q3.2(BASE) R33.2
N24168984: Q1.2(BASE) Q2.3(COLLECTOR) R31.2
N24169394: Q1.1(EMITTER) R30.2
N24172346: D3.1(CATHODE) Q1.3(COLLECTOR)
N24174442: Q5.2(BASE) Q6.3(COLLECTOR) R40.2
N24174452: Q4.2(BASE) Q5.3(COLLECTOR) R39.2
N24174456: Q4.1(EMITTER) R38.2
N24181679: Q7.1(EMITTER) R37.2
N24182132: Q7.3(COLLECTOR) Q8.2(BASE) R36.1
N24183420: Q8.3(COLLECTOR) Q9.2(BASE) R35.2
N24185271: Q9.1(EMITTER) R34.1
N24257930: Q6.2(BASE) R41.2
N24682413: J2.1 J2.3 R43.2
N24837999: C35.1 L2.1 P1.1B P1.1C
N24838077: C55.1 L4.1 P1.25E P1.25F
N24838289: C36.1 C37.1 L2.2 R44.2
N24838878: C53.1 C54.1 L4.2 R42.1

Not connected (* = marked no-connect by the designer): U1 2(FB4)* 3(BASE)*; U3 B11(NC1)* C11(NC2)* C13(NC3)* E12(NC4)* E14(NC5)* E23(NC6)* H4(NC7)* N2(NC8)* N3(NC9)* N4(NC10)* R2(NC11)* R3(NC12)* R4(NC13)* T4(NC14)* U2(NC15)* U3(NC16)* U4(NC17)* W3(NC18)* W4(NC19)* W5(NC20)* W13(NC21)* W14(NC22)* W23(NC23)* X4(NC24)* X5(NC25)* X13(NC26)* Y2(NC27)* Y3(NC28)* Y4(NC29)* Y5(NC30)* Z11(NC31)*

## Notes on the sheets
sheet 1
- DMD POWER
- 10/13/21
sheet 2
- DO NOT INSTALL
- DMD DATA INPUT
- 10/13/21
sheet 3
- COMPUTER GENERATED DRAWING.  DO NOT REVISE MANUALLY
- NOTES, UNLESS OTHERWISE SPECIFIED:
- REVISIONS
- 1. The netname "DMD_P3P3V" represents connection to the +3.3V digital power plane.
- REV
- DESCRIPTION
- DATE
- APPROVED
- 2. The symbol
- represents connection to the digital ground plane.
- A
- ECO 2117139: Initial Release
- 9/13/2011
- 3. A "Z" suffix on a signal name indicates an active low signal.
- B
- ECO 2123014: Added DAD_OEZ Delay Circuit
- 3/07/2012
- 4. All components with designators "U", "D", "Y" and "Q" are electrostatic discharge sensitive.
- 5. All resistor values are in ohms, 1/16W and 5% unless otherwise specified.
- Page 2 - R29 changed from 10K Ohm to 1K Ohm
- Page 2 - Added C111 2700pF
- 6. 470 Ohm resistors R1, R2, R3, R4, R6, and R9 protect
      the system when/if wrong DMD is installed on-board.
- C
- Changed U1000 from DLP6500FYE to DLP6500BFYE
- 10/13/2021
- HIGHEST REFERENCE DESIGNATORS USED
- C111
- D3
- DN2
- J2
- L4
- P1
- R45
- TP38
- U1000
- Q9
- 2511981
- 0314SS
sheet 4
- 3.3V
- Do Not Install Jumper
  if DMD is mounted
- 8.5V
- -10V
- 16.0V
- DMD POWER SUPPLY
- 10/13/21
sheet 5
- Note: Only install one 1K Ohm pull-up
  resistor on DAD_OEZ. If DAD_OEZ pull-up
  is installed on Main board side, do not
  install R29.
- Note: R6 and C111 are specific values
  selected to delay ASIC driven DAD_OEZ to
  allow the DMD enough time to park properly.
  Recommend installing values as shown.
- Test Only - Not for Production
- 470 Ohm resistors R1, R2, R3, R4, R6, and R9 protect
  the system when/if wrong DMD is installed on-board.
- If installing R43 to connect
  DMD_P3P3V to external power
  supply, uninstall R42, R44
- INPUT CONNECTOR
- 10/13/21
